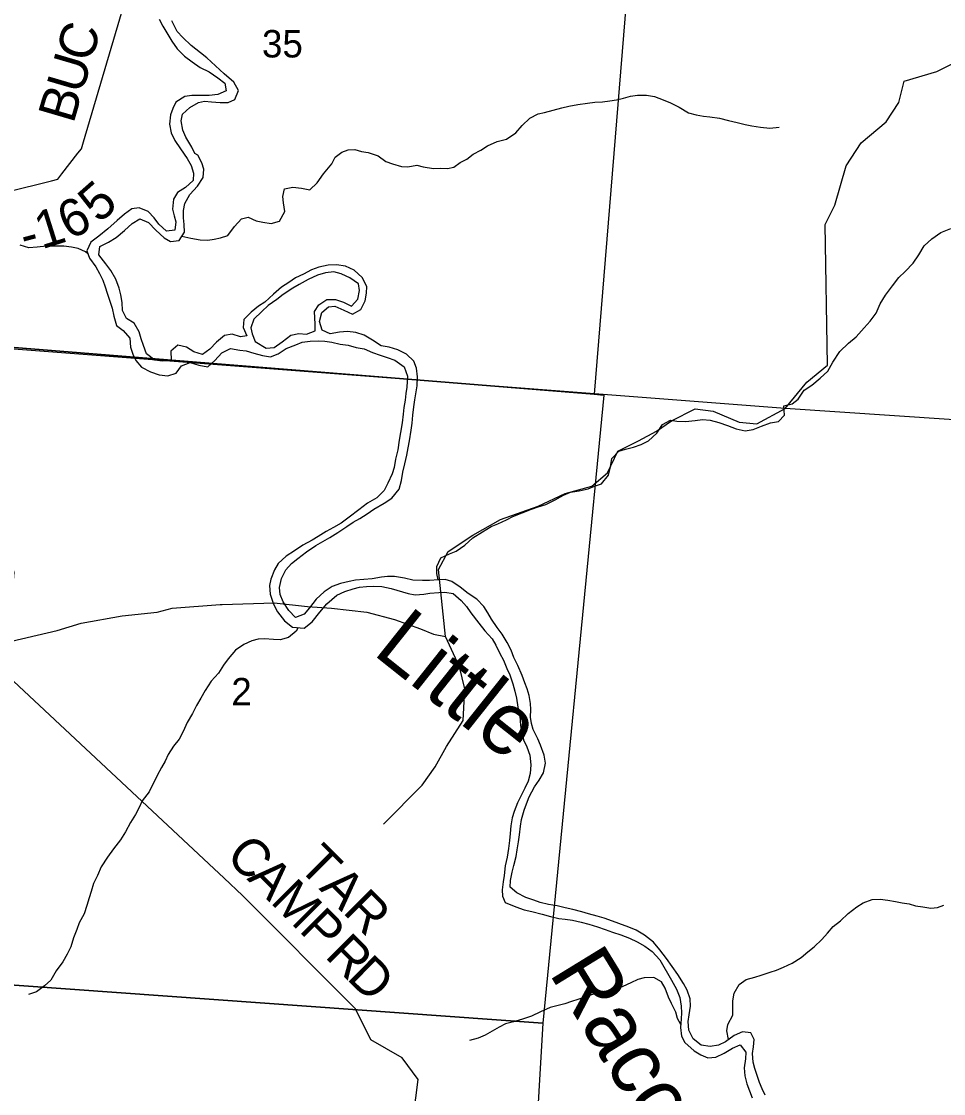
# Model space of a CAD drawing. Extents: x 0 to 42, y 0 to 22.
# Drawn here: x 7.577 to 8.279, y 19.536 to 20.353 of the extents above; entities that cross this region are included whole.
import ezdxf

# ---------------------------------------------------------------- set-up
doc = ezdxf.new("R2010")
doc.units = 0
for name, color, linetype in [('GM_X_Major_River', 7, 'Continuous'), ('GM_X_Major_River_Text', 7, 'Continuous'), ('GM_X_Minor_River', 7, 'Continuous'), ('GM_X_Section', 7, 'Continuous'), ('GM_X_Section_Text', 7, 'Continuous'), ('GM_X_Township', 7, 'Continuous'), ('GM_X_Township_Road', 7, 'Continuous'), ('GM_X_Township_Road_Text', 7, 'Continuous')]:
    doc.layers.add(name, color=color, linetype=linetype)

msp = doc.modelspace()

# ---------------------------------------------------------------- linework, layer by layer
at = {"layer": 'GM_X_Major_River'}
for points in [[(7.66139, 20.19923), (7.66729, 20.20278), (7.6739, 20.19988), (7.67934, 20.19396), (7.68573, 20.18822), (7.69063, 20.18534), (7.69708, 20.18623), (7.7013, 20.19245), (7.70097, 20.19833), (7.70044, 20.20345), (7.70049, 20.20914), (7.70148, 20.21444), (7.70533, 20.22123), (7.71125, 20.22744), (7.71548, 20.23423), (7.71591, 20.24048), (7.71443, 20.24523), (7.71126, 20.25113), (7.70919, 20.25248), (7.70677, 20.25723), (7.70229, 20.26485), (7.69987, 20.27018), (7.6986, 20.27739), (7.69978, 20.2825), (7.70532, 20.28757), (7.71179, 20.29131), (7.71653, 20.29222), (7.72183, 20.2918), (7.72846, 20.29137), (7.73452, 20.29131), (7.73946, 20.29355), (7.74236, 20.30035), (7.73881, 20.30682), (7.73148, 20.31314), (7.72471, 20.31926), (7.71833, 20.32538), (7.71344, 20.32921), (7.70629, 20.33476), (7.6999, 20.34069), (7.69577, 20.34547), (7.69167, 20.35346)], [(7.68184, 20.35487), (7.68482, 20.34954), (7.69154, 20.33811), (7.69566, 20.3322), (7.70129, 20.32666), (7.70694, 20.32225), (7.71315, 20.31784), (7.72013, 20.31456), (7.72653, 20.30996), (7.73199, 20.30612), (7.73307, 20.30005), (7.72661, 20.29726), (7.71998, 20.29674), (7.71392, 20.2966), (7.70672, 20.29666)], [(7.70672, 20.29666), (7.7016, 20.29595), (7.69475, 20.29164), (7.69225, 20.28673), (7.6905, 20.28182), (7.68968, 20.27481), (7.69114, 20.26817), (7.69374, 20.26246), (7.69823, 20.25598), (7.70329, 20.24873), (7.70627, 20.24321), (7.70812, 20.23751), (7.70788, 20.23182), (7.70196, 20.22657), (7.69587, 20.22282), (7.6928, 20.21754), (7.69216, 20.20997), (7.69326, 20.20503), (7.69454, 20.20028), (7.69392, 20.19403), (7.68748, 20.19332), (7.68165, 20.19849), (7.67809, 20.20345), (7.67359, 20.20822), (7.66661, 20.21112), (7.66111, 20.21022), (7.65558, 20.20629), (7.65005, 20.2014), (7.6428, 20.19502), (7.63593, 20.18958), (7.62983, 20.18489), (7.62675, 20.17828), (7.62878, 20.17258), (7.63365, 20.16609), (7.63645, 20.16114), (7.63906, 20.156), (7.64072, 20.15087), (7.64238, 20.14612), (7.64386, 20.14136), (7.64608, 20.13471), (7.64754, 20.12844), (7.64956, 20.12141), (7.65464, 20.11758), (7.65952, 20.11185), (7.66022, 20.10502), (7.66188, 20.09951), (7.66411, 20.09475), (7.66842, 20.08979), (7.67521, 20.08613), (7.68182, 20.0838), (7.68844, 20.08318), (7.6949, 20.08521), (7.69892, 20.09067), (7.70557, 20.09327), (7.71218, 20.09132), (7.71899, 20.08994), (7.72433, 20.09464), (7.72969, 20.10066), (7.73615, 20.10383), (7.74334, 20.10263), (7.74826, 20.10202), (7.75393, 20.10046), (7.76073, 20.09851), (7.76678, 20.09751), (7.77267, 20.09973), (7.77877, 20.10385), (7.78599, 20.10664), (7.79074, 20.10869), (7.797, 20.10958), (7.80325, 20.10972), (7.80817, 20.10949), (7.81346, 20.10869), (7.8197, 20.10731), (7.82576, 20.10631), (7.83199, 20.10474), (7.83804, 20.10356), (7.84446, 20.10085), (7.85031, 20.09891), (7.8556, 20.09697), (7.86145, 20.09502), (7.86861, 20.09004), (7.87101, 20.08281), (7.87056, 20.07448), (7.86976, 20.06955), (7.86915, 20.06444), (7.86835, 20.05895), (7.86774, 20.05383), (7.86692, 20.04721), (7.86573, 20.04001), (7.86473, 20.03396), (7.86372, 20.02676), (7.86195, 20.01957), (7.86077, 20.01333), (7.8594, 20.00841), (7.85612, 20.00123), (7.85323, 19.99576), (7.84769, 19.99012), (7.84065, 19.986), (7.83398, 19.98094), (7.82673, 19.97531), (7.82044, 19.97082)], [(7.78269, 19.94023), (7.78746, 19.94398), (7.79413, 19.94904), (7.80136, 19.95391), (7.80669, 19.9569), (7.81183, 19.95989), (7.81811, 19.96382), (7.82478, 19.96832), (7.82973, 19.9715), (7.83468, 19.97449), (7.84039, 19.97785), (7.84553, 19.98141), (7.85334, 19.98609), (7.85924, 19.98983), (7.86479, 19.9968), (7.86655, 20.00323), (7.86755, 20.00967), (7.86912, 20.0161), (7.8705, 20.02272), (7.8715, 20.02821), (7.87249, 20.03351), (7.87388, 20.04165), (7.87449, 20.04696), (7.87512, 20.05321), (7.87593, 20.05945), (7.87654, 20.06476), (7.87852, 20.07536), (7.87858, 20.08237), (7.87788, 20.08882), (7.87584, 20.09415), (7.8702, 20.0995), (7.8636, 20.10297), (7.85699, 20.10492), (7.85094, 20.10591), (7.84435, 20.11033), (7.83813, 20.11417), (7.83171, 20.11612), (7.82528, 20.11693), (7.81921, 20.11641), (7.81219, 20.11514), (7.80597, 20.11785), (7.80394, 20.1245), (7.8057, 20.13131), (7.81085, 20.13563), (7.81578, 20.13616), (7.82257, 20.13307), (7.82918, 20.13017), (7.83545, 20.13353), (7.83873, 20.14014), (7.83991, 20.146), (7.83996, 20.15112), (7.83642, 20.15797), (7.8304, 20.16352), (7.8238, 20.16661), (7.81699, 20.16761), (7.81055, 20.16729), (7.80353, 20.16583), (7.79783, 20.16379), (7.79175, 20.16062), (7.78585, 20.15763), (7.78071, 20.15426), (7.77518, 20.15071), (7.76889, 20.14526), (7.7624, 20.13906), (7.75764, 20.13607), (7.75211, 20.13156), (7.74638, 20.12592), (7.74595, 20.11986), (7.74874, 20.11358), (7.74381, 20.11286), (7.73757, 20.11481), (7.73169, 20.11391), (7.72559, 20.10865), (7.72062, 20.10339), (7.7149, 20.09926), (7.70829, 20.1014), (7.70264, 20.10486), (7.69621, 20.10643), (7.69087, 20.10193), (7.691, 20.09491), (7.68456, 20.09421), (7.67851, 20.09501), (7.6723, 20.0998), (7.66989, 20.10627), (7.66823, 20.11121), (7.66676, 20.11653), (7.66284, 20.1232), (7.65718, 20.12685), (7.65401, 20.13275), (7.65369, 20.13901), (7.65279, 20.1447), (7.65151, 20.14983), (7.64891, 20.15668), (7.64518, 20.16334), (7.64125, 20.1683), (7.636, 20.17517), (7.63681, 20.18161), (7.64328, 20.18478), (7.64918, 20.18833), (7.65566, 20.19377), (7.66139, 20.19923)], [(7.82096, 20.16045), (7.82043, 20.16068), (7.81495, 20.16219), (7.80872, 20.16143), (7.80249, 20.15973), (7.7955, 20.1565), (7.78852, 20.15271), (7.78361, 20.14987), (7.77643, 20.14494), (7.77152, 20.14133), (7.76492, 20.1366), (7.76001, 20.13205), (7.75397, 20.12636), (7.7517, 20.11973), (7.75284, 20.11499), (7.75511, 20.1093)], [(7.75511, 20.1093), (7.76342, 20.10419), (7.76946, 20.10476), (7.7755, 20.10893), (7.78211, 20.11405), (7.78834, 20.11538), (7.7942, 20.11481), (7.80062, 20.11728), (7.8008, 20.12239), (7.80042, 20.12713), (7.80023, 20.13206), (7.80344, 20.13717), (7.80967, 20.14116), (7.81628, 20.14116), (7.82232, 20.13926), (7.82837, 20.13604), (7.83328, 20.14135), (7.83441, 20.14798), (7.83365, 20.1531), (7.82704, 20.15784), (7.82096, 20.16045)], [(7.82044, 19.97082), (7.81474, 19.96764), (7.80903, 19.96446), (7.80313, 19.96072), (7.79837, 19.95792), (7.79133, 19.95399), (7.78504, 19.94988), (7.77857, 19.94557), (7.77246, 19.94012), (7.76977, 19.93521), (7.76687, 19.92822), (7.76588, 19.9233), (7.76639, 19.91666), (7.76898, 19.90925), (7.77215, 19.90335), (7.77739, 19.89648), (7.7836, 19.89169), (7.79231, 19.89086), (7.79841, 19.89555), (7.80434, 19.90308), (7.80951, 19.9093), (7.81733, 19.91606), (7.82323, 19.91885), (7.82968, 19.92088), (7.83462, 19.92198), (7.83993, 19.92269), (7.84485, 19.92284), (7.85148, 19.9226), (7.85866, 19.92102), (7.87151, 19.91713), (7.8768, 19.91632), (7.88344, 19.91684), (7.88818, 19.91756), (7.89481, 19.91807), (7.89954, 19.91822), (7.90579, 19.91722), (7.9118, 19.91205), (7.91593, 19.90728), (7.9193, 19.90251), (7.92548, 19.89469), (7.92998, 19.88878), (7.93561, 19.88267), (7.93822, 19.8779), (7.94138, 19.87162), (7.94418, 19.86648), (7.94659, 19.86021), (7.94901, 19.85526), (7.95123, 19.84841), (7.95269, 19.8429), (7.95397, 19.8374), (7.95505, 19.83056), (7.95651, 19.82392), (7.95721, 19.8169), (7.95793, 19.81215), (7.95939, 19.80569), (7.96181, 19.80036), (7.96421, 19.79409), (7.96491, 19.78669), (7.96448, 19.78006), (7.96291, 19.77438), (7.9604, 19.76891), (7.9579, 19.764), (7.95482, 19.75777), (7.9523, 19.75115), (7.95074, 19.74624), (7.94975, 19.74037), (7.94913, 19.73431), (7.94871, 19.72919), (7.94809, 19.72313), (7.94689, 19.71632), (7.94551, 19.70969), (7.94469, 19.7025), (7.94389, 19.69757), (7.94309, 19.69151), (7.94342, 19.68677), (7.94547, 19.68183), (7.95358, 19.67854), (7.96, 19.6764), (7.96586, 19.67502), (7.97361, 19.67287), (7.98003, 19.67112), (7.98627, 19.66974), (7.99119, 19.66913), (7.99668, 19.66832), (8.00329, 19.66694), (8.00915, 19.66538), (8.01576, 19.66324), (8.02162, 19.6613), (8.02728, 19.65916), (8.03351, 19.65722), (8.04012, 19.6547), (8.04597, 19.65199), (8.05181, 19.64853), (8.05746, 19.64451), (8.06309, 19.63821), (8.07205, 19.62278), (8.07596, 19.61573), (8.07856, 19.60945), (8.07946, 19.603), (8.0796, 19.59788), (8.07937, 19.59314)], [(8.10154, 19.5723), (8.09473, 19.57311), (8.08852, 19.5779), (8.08517, 19.58456), (8.08485, 19.5912), (8.08546, 19.59631), (8.08646, 19.60294), (8.08632, 19.60844), (8.08391, 19.6151), (8.0813, 19.62005), (8.07682, 19.62691), (8.07251, 19.6332), (8.06821, 19.6393), (8.06315, 19.64579), (8.05828, 19.6517), (8.0515, 19.65707), (8.04509, 19.66072), (8.03962, 19.66304), (8.03207, 19.66576), (8.02716, 19.66769), (8.02093, 19.66983), (8.01545, 19.67158), (8.00884, 19.67334), (8.00374, 19.67471), (7.99693, 19.67647), (7.99107, 19.67785), (7.98503, 19.67942), (7.97841, 19.68042), (7.97217, 19.68199), (7.96726, 19.68354), (7.96122, 19.68568), (7.95443, 19.68915), (7.94916, 19.69355), (7.9494, 19.69867), (7.95077, 19.70491), (7.95214, 19.71002), (7.95372, 19.71683), (7.95452, 19.72194), (7.95551, 19.728), (7.95632, 19.7333), (7.95713, 19.73993), (7.95793, 19.74504), (7.95988, 19.75223), (7.96163, 19.75714), (7.96376, 19.76243), (7.9678, 19.76998), (7.97144, 19.77507), (7.97471, 19.78054), (7.9761, 19.78812), (7.97501, 19.794), (7.97242, 19.8016), (7.97019, 19.80655), (7.96665, 19.8136), (7.96537, 19.81834), (7.96484, 19.82309), (7.96489, 19.82878), (7.96474, 19.83352), (7.96365, 19.83959), (7.96218, 19.84453), (7.96032, 19.84929), (7.95829, 19.8548), (7.95513, 19.86241), (7.95215, 19.8685), (7.94993, 19.87402), (7.94695, 19.87992), (7.94302, 19.8864), (7.93928, 19.89136), (7.93498, 19.89783), (7.93218, 19.9026), (7.92919, 19.90736), (7.92374, 19.9129), (7.91734, 19.91713), (7.91113, 19.92211), (7.90473, 19.92652), (7.89982, 19.92789), (7.8947, 19.92774), (7.88769, 19.92723), (7.88239, 19.92708), (7.875, 19.92733), (7.86877, 19.9289), (7.8612, 19.9301), (7.8559, 19.93015), (7.85116, 19.92962), (7.84414, 19.92854), (7.83789, 19.92783), (7.83144, 19.9275), (7.8267, 19.92641), (7.82006, 19.92494), (7.8136, 19.92253), (7.80751, 19.9186), (7.80159, 19.91296), (7.79642, 19.90637), (7.7924, 19.90147), (7.78575, 19.89887), (7.78068, 19.90441), (7.77638, 19.91089), (7.77396, 19.91641), (7.77363, 19.92172), (7.77502, 19.92873), (7.77829, 19.93533), (7.78269, 19.94023)], [(8.07937, 19.59314), (8.07894, 19.5867), (8.07983, 19.58006), (8.08225, 19.57511), (8.08939, 19.56879), (8.09448, 19.56572), (8.09977, 19.56359), (8.10583, 19.56411), (8.1121, 19.56709), (8.11858, 19.57102), (8.12428, 19.57344), (8.12859, 19.5679), (8.12836, 19.56279), (8.12754, 19.55597), (8.12806, 19.54971), (8.12952, 19.54382), (8.13137, 19.53831), (8.1336, 19.53298)], [(8.14346, 19.53499), (8.14104, 19.53993), (8.13919, 19.54469), (8.13716, 19.55077), (8.13549, 19.55553), (8.13421, 19.56027), (8.13369, 19.56672), (8.13449, 19.57203), (8.13511, 19.57752), (8.1325, 19.58266), (8.12626, 19.58328), (8.1198, 19.58068), (8.11313, 19.5758), (8.1078, 19.57319), (8.10154, 19.5723)]]:
    msp.add_lwpolyline(points, dxfattribs=at)
at = {"layer": 'GM_X_Minor_River'}
for points in [[(7.69928, 20.18948), (7.70605, 20.18789), (7.71324, 20.18674), (7.71892, 20.18653), (7.72385, 20.18727), (7.72858, 20.18821), (7.73427, 20.19009), (7.73921, 20.19671), (7.74471, 20.20256), (7.74964, 20.20388), (7.75588, 20.20121), (7.7608, 20.20005), (7.76723, 20.19909), (7.77367, 20.20096), (7.77767, 20.20815), (7.77674, 20.21479), (7.776, 20.21972), (7.77734, 20.2254), (7.78378, 20.2269), (7.79041, 20.22593), (7.79665, 20.22478), (7.80215, 20.23007), (7.8071, 20.23707), (7.81337, 20.24463), (7.81584, 20.24955), (7.82097, 20.25351), (7.82589, 20.25521), (7.83082, 20.25557), (7.83592, 20.25404), (7.84103, 20.25327), (7.84859, 20.25059), (7.85464, 20.2464), (7.85955, 20.24449), (7.86636, 20.24258), (7.87128, 20.24237), (7.8781, 20.24349), (7.88302, 20.24234), (7.89077, 20.24099), (7.89645, 20.24116), (7.90156, 20.24096), (7.9063, 20.24208), (7.91104, 20.24548), (7.91635, 20.24812), (7.92109, 20.25189), (7.92697, 20.2551), (7.9319, 20.2583), (7.93929, 20.26169), (7.94649, 20.26338), (7.95351, 20.26829), (7.95826, 20.27377), (7.96433, 20.27925), (7.97059, 20.28264), (7.97533, 20.28376), (7.98859, 20.28714), (7.99389, 20.28845), (8.00071, 20.28975), (8.00809, 20.29068), (8.01377, 20.29142), (8.01964, 20.29178), (8.02514, 20.29253), (8.03025, 20.29327), (8.03555, 20.29458), (8.04086, 20.29608), (8.04616, 20.29682), (8.05316, 20.2968), (8.05922, 20.29584), (8.06564, 20.29335), (8.07132, 20.29106), (8.07793, 20.28763), (8.08511, 20.28344), (8.09078, 20.28191), (8.09646, 20.28094), (8.10138, 20.28036), (8.10857, 20.27939), (8.11556, 20.27767), (8.12199, 20.27594), (8.12824, 20.2746), (8.13315, 20.27345), (8.13978, 20.27248), (8.14697, 20.2717), (8.15397, 20.27244)], [(7.89439, 19.92772), (7.89339, 19.93241), (7.89341, 19.93772), (7.89646, 19.94434), (7.90309, 19.94755), (7.90821, 19.94962), (7.91466, 19.95415), (7.92073, 19.95963), (7.92813, 19.96434), (7.93477, 19.9683), (7.93989, 19.97037), (7.94652, 19.97339), (7.95126, 19.97603), (7.95827, 19.97866), (7.96547, 19.98148), (7.97059, 19.98317), (7.97646, 19.98505), (7.98348, 19.98863), (7.98993, 19.99221), (7.99523, 19.99447), (8.00186, 19.9954), (8.00868, 19.99709), (8.01342, 19.99897), (8.01872, 20.00085), (8.02423, 20.00728), (8.02558, 20.01372), (8.02673, 20.02016), (8.03205, 20.02564), (8.03698, 20.02714), (8.04323, 20.02883), (8.0491, 20.03071), (8.0546, 20.03353), (8.06087, 20.03939), (8.06524, 20.04601), (8.07131, 20.04941), (8.07623, 20.04864), (8.08285, 20.04824), (8.09005, 20.04916), (8.09573, 20.04972), (8.10159, 20.04932), (8.10821, 20.04741), (8.11483, 20.0453), (8.12144, 20.04282), (8.12825, 20.04128), (8.13431, 20.04221), (8.14057, 20.04466), (8.14739, 20.04729), (8.15364, 20.04822), (8.1582, 20.05314), (8.15765, 20.06015), (8.1639, 20.06165), (8.16865, 20.06542), (8.17302, 20.07224), (8.1789, 20.07601), (8.18535, 20.0813), (8.19105, 20.08659), (8.19486, 20.09359), (8.20018, 20.10172), (8.20683, 20.10796), (8.21271, 20.11287), (8.21879, 20.11968), (8.22335, 20.12459), (8.22791, 20.13083), (8.23096, 20.13784), (8.23496, 20.14446), (8.24028, 20.15165), (8.24522, 20.15807), (8.25016, 20.16261), (8.25604, 20.16885), (8.26042, 20.17528), (8.2646, 20.18209), (8.2703, 20.18738), (8.27732, 20.19229), (8.2849, 20.1953)], [(7.62747, 20.17625), (7.62571, 20.17764), (7.62028, 20.18019), (7.61518, 20.18115), (7.60931, 20.18192), (7.60288, 20.18194), (7.59625, 20.18177), (7.58906, 20.18104), (7.58262, 20.18049), (7.57619, 20.18259)], [(7.78789, 19.89128), (7.78631, 19.88856), (7.78043, 19.88384), (7.77418, 19.88196), (7.76906, 19.88217), (7.76225, 19.88276), (7.75733, 19.88258), (7.75241, 19.88127), (7.74653, 19.87844), (7.74008, 19.8741), (7.73457, 19.86748), (7.73096, 19.86257), (7.72715, 19.85651), (7.72164, 19.85046), (7.71708, 19.84327), (7.71365, 19.8376), (7.71042, 19.83192), (7.70737, 19.82586), (7.70337, 19.81905), (7.70032, 19.81205), (7.69728, 19.80637), (7.69291, 19.80088), (7.68891, 19.79464), (7.68643, 19.78953), (7.68377, 19.78461), (7.68053, 19.77874), (7.67425, 19.76625), (7.66892, 19.75925), (7.66664, 19.75414), (7.66397, 19.74884), (7.65998, 19.74279), (7.65636, 19.7356), (7.65255, 19.72954), (7.64704, 19.72273), (7.64248, 19.7163), (7.63772, 19.70911), (7.63505, 19.70249), (7.632, 19.69643), (7.63009, 19.69037), (7.62875, 19.68545), (7.62684, 19.67958), (7.62493, 19.67314), (7.62093, 19.66632), (7.61921, 19.66121), (7.61673, 19.65496), (7.61463, 19.64815), (7.61196, 19.64247), (7.60853, 19.6366), (7.6034, 19.62979), (7.5994, 19.62279), (7.59466, 19.61844), (7.58859, 19.61391), (7.58234, 19.61185)], [(8.11551, 19.57755), (8.11413, 19.58414), (8.11509, 19.58906), (8.1189, 19.59606), (8.11891, 19.60118), (8.11874, 19.60687), (8.11971, 19.61274), (8.12351, 19.61937), (8.12902, 19.62314), (8.13546, 19.62502), (8.14038, 19.62652), (8.1472, 19.62877), (8.15213, 19.63028), (8.15744, 19.63272), (8.16388, 19.63555), (8.1709, 19.64008), (8.17583, 19.64423), (8.18077, 19.6482), (8.18665, 19.65368), (8.19083, 19.6586), (8.1952, 19.6637), (8.2007, 19.66786), (8.20659, 19.67353), (8.21323, 19.67862), (8.21797, 19.68164), (8.22498, 19.68409), (8.23104, 19.68445), (8.23672, 19.68367), (8.24258, 19.68271), (8.24788, 19.68156), (8.25298, 19.68078), (8.2579, 19.67944), (8.26339, 19.67848), (8.26963, 19.67751), (8.27455, 19.67807), (8.27948, 19.67995)], [(8.07909, 19.58898), (8.07668, 19.59353), (8.07537, 19.59828), (8.07198, 19.60492), (8.06992, 19.60985), (8.06729, 19.61668), (8.06447, 19.62143), (8.05861, 19.62467), (8.05123, 19.6245), (8.04649, 19.62319), (8.04118, 19.62055), (8.03512, 19.61792), (8.02962, 19.61547), (8.02451, 19.61435), (8.01806, 19.61266), (8.01276, 19.61192), (8.00082, 19.60797), (7.9959, 19.60647), (7.99078, 19.60478), (7.9798, 19.60178), (7.97221, 19.59858), (7.96558, 19.59518), (7.95857, 19.59293), (7.95175, 19.59086), (7.94569, 19.58937), (7.94095, 19.58691), (7.93545, 19.5839), (7.93014, 19.58088), (7.92483, 19.57862), (7.9182, 19.57674)]]:
    msp.add_lwpolyline(points, dxfattribs=at)
at = {"layer": 'GM_X_Section'}
for points in [[(7.53847, 20.6135), (8.05463, 20.57604), (8.01309, 20.06914), (7.51128, 20.10951), (7.49972, 20.11083)], [(7.51128, 20.10951), (8.01309, 20.06914), (8.02067, 20.06839), (7.97421, 19.59006), (7.47278, 19.62588)], [(7.47278, 19.62588), (7.97421, 19.59006), (7.94388, 19.07499), (7.43468, 19.11252)]]:
    msp.add_lwpolyline(points, close=True, dxfattribs=at)
at = {"layer": 'GM_X_Township'}
msp.add_lwpolyline([(6.30624, 20.21096), (6.44864, 20.19642), (6.46255, 20.19541), (6.50517, 20.19232), (6.97769, 20.15098), (7.46606, 20.1144), (7.51155, 20.10827), (8.15853, 20.05855), (8.5294, 20.03351), (8.48531, 19.43126)], dxfattribs=at)
at = {"layer": 'GM_X_Township_Road'}
msp.add_lwpolyline([(8.604, 20.9), (5.44663, 20.9), (5.4327, 20.74917), (5.43171, 20.7371), (5.43118, 20.73056), (5.42978, 20.72026), (5.42813, 20.71602), (5.40834, 20.52112), (5.38817, 20.287), (5.7544, 20.26066), (6.25694, 20.21504), (6.30624, 20.21096), (6.44864, 20.19642), (6.46255, 20.19541), (6.50517, 20.19232), (6.97769, 20.15098), (7.46606, 20.1144), (7.51155, 20.10827), (8.15853, 20.05855), (8.5294, 20.03351), (8.55155, 20.24789), (8.57059, 20.47391), (8.6039, 20.89865)], close=True, dxfattribs=at)
for points in [[(7.56615, 20.22329), (7.59992, 20.23171), (7.60468, 20.2329), (7.60777, 20.23687), (7.61998, 20.25257), (7.62269, 20.25606), (7.62426, 20.26135), (7.6554, 20.3662)], [(8.19427, 20.20844), (8.19659, 20.21307), (8.20508, 20.24308), (8.21641, 20.26063), (8.23566, 20.27649), (8.24529, 20.29121), (8.24925, 20.30763), (8.27417, 20.31499), (8.30021, 20.32802)], [(7.56194, 19.87916), (7.60428, 19.88904), (7.62263, 19.89469), (7.65368, 19.90033), (7.6805, 19.90315), (7.69179, 19.90597), (7.72848, 19.9088), (7.7299, 19.9088), (7.76941, 19.91021), (7.79482, 19.90738), (7.81317, 19.90597), (7.83998, 19.90314), (7.86115, 19.8975), (7.88091, 19.89044), (7.89079, 19.88621), (7.89989, 19.88439), (7.89476, 19.9356), (7.90213, 19.94918), (7.92082, 19.96164), (7.94176, 19.97354), (7.97065, 19.98373), (7.99103, 19.99335), (8.01142, 19.99902), (8.02331, 20.00921), (8.03124, 20.02563), (8.04709, 20.03356), (8.06068, 20.04092), (8.07201, 20.04885), (8.09013, 20.05791), (8.10372, 20.05621), (8.12354, 20.04772), (8.13713, 20.04658), (8.15863, 20.05829), (8.17507, 20.0783), (8.19092, 20.09132), (8.18923, 20.19834), (8.19427, 20.20844)], [(7.73135, 19.70049), (7.54371, 19.87589), (7.55233, 19.88857), (7.567, 19.90302), (7.56958, 19.90989), (7.57161, 19.93322), (7.56806, 19.94439), (7.5498, 19.95708), (7.51225, 19.9723), (7.49093, 19.98194), (7.47368, 19.98245), (7.45509, 19.98841)], [(7.85269, 19.74154), (7.88233, 19.77117), (7.89221, 19.78529), (7.90068, 19.80082), (7.91338, 19.82058), (7.91479, 19.84457), (7.91055, 19.86151), (7.89989, 19.88439)], [(7.94846, 19.43819), (7.94087, 19.44137), (7.92544, 19.45271), (7.91599, 19.46134), (7.89307, 19.46792), (7.8769, 19.4896), (7.87551, 19.51908), (7.87928, 19.54711), (7.86706, 19.56358), (7.84323, 19.57736), (7.83141, 19.60085), (7.74548, 19.68729), (7.73135, 19.70049)]]:
    msp.add_lwpolyline(points, dxfattribs=at)

# ---------------------------------------------------------------- texts
at = {"layer": 'GM_X_Major_River_Text'}
for s, height, rotation, p in [('Little', 0.047351, 321.50917, (7.84365, 19.87162)), ('Raccoon', 0.047353, 301.51021, (7.97824, 19.62843))]:
    msp.add_text(s, height=height, rotation=rotation, dxfattribs=at).set_placement(p)
at = {"layer": 'GM_X_Section_Text'}
for s, height, p in [('35', 0.020928, (7.76022, 20.32559)), ('2', 0.02093, (7.73688, 19.83199))]:
    msp.add_text(s, height=height, rotation=0.00001, dxfattribs=at).set_placement(p)
at = {"layer": 'GM_X_Township_Road_Text'}
for s, height, rotation, p in [('C', 0.02841, 73.95444, (7.63024, 20.32109)), ('U', 0.02841, 73.62306, (7.62314, 20.29693)), ('B', 0.02841, 73.61926, (7.61656, 20.27455)), ('5', 0.02841, 41.42388, (7.63612, 20.1986)), ('6', 0.02841, 26.03875, (7.6135, 20.18632)), ('1', 0.02841, 17.45536, (7.5925, 20.17935)), ('-', 0.02841, 14.86718, (7.57988, 20.17597)), ('C', 0.02841, 315, (7.7317, 19.71621)), ('TAR', 0.028409, 315, (7.78673, 19.70874)), ('A', 0.02841, 315, (7.7482, 19.69971)), ('M', 0.02841, 315, (7.76588, 19.68204)), ('P', 0.02841, 315, (7.78768, 19.66023)), ('R', 0.02841, 315.02473, (7.80743, 19.64048)), ('D', 0.02841, 315.34125, (7.82406, 19.62387))]:
    msp.add_text(s, height=height, rotation=rotation, dxfattribs=at).set_placement(p)

doc.saveas('drawing.dxf')
